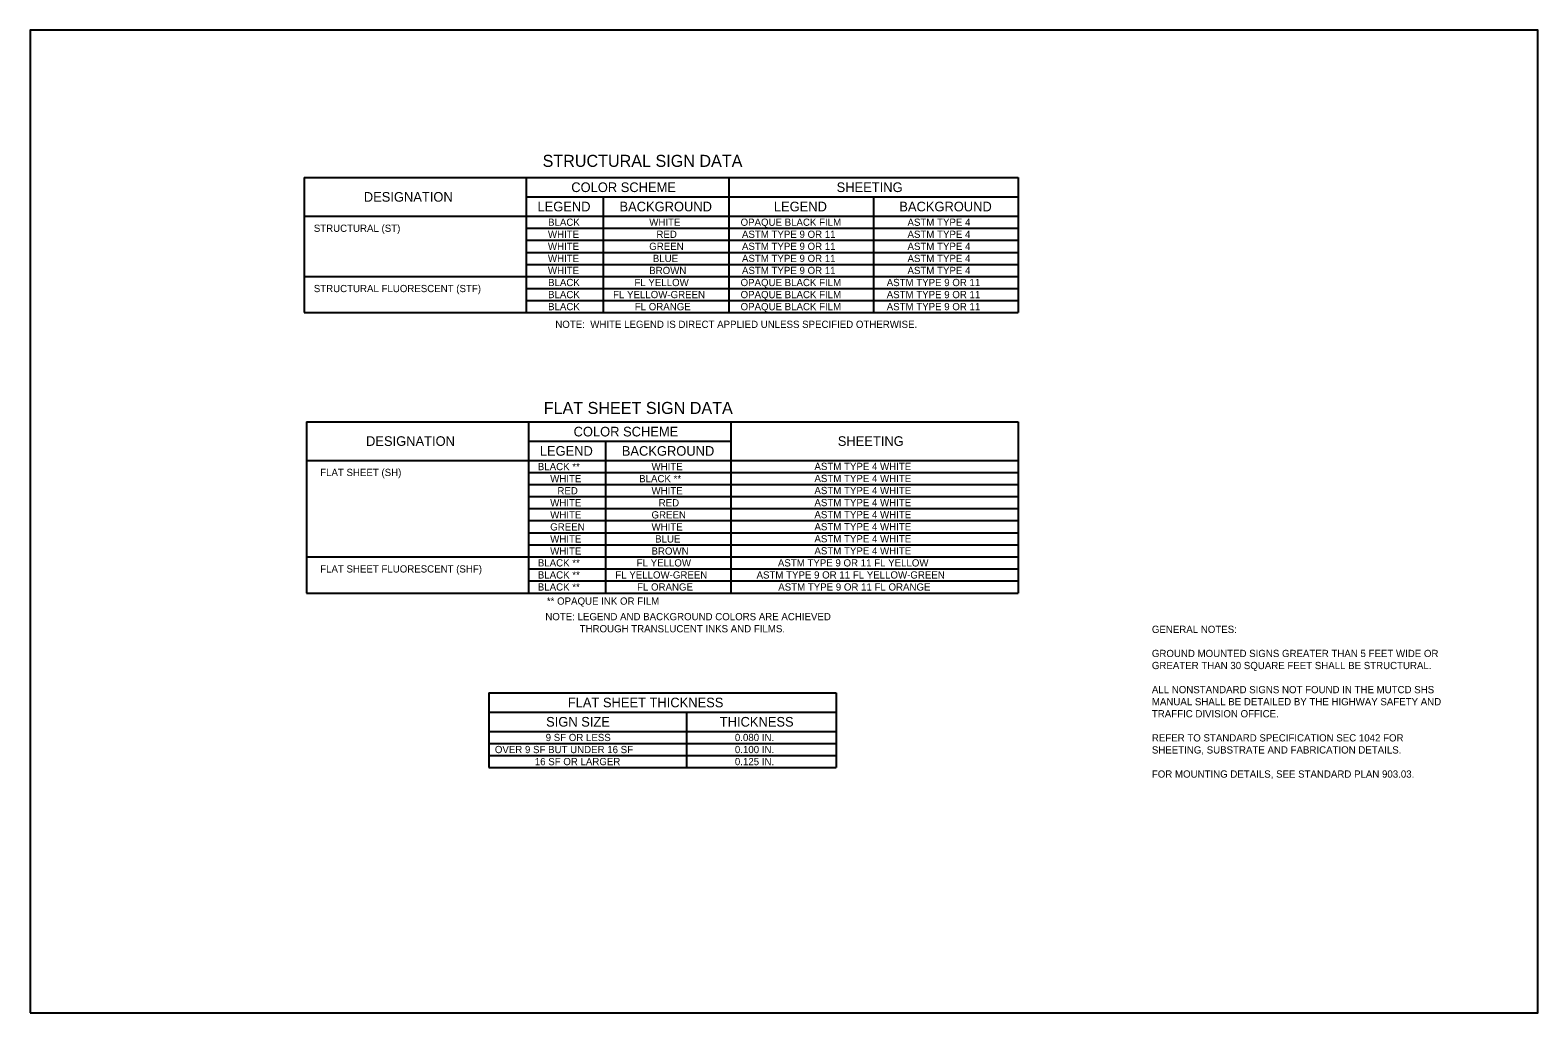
# Model space of a CAD drawing. Extents: x -439.1 to -407.9, y -458.1 to -437.7.
import ezdxf

# ---------------------------------------------------------------- set-up
doc = ezdxf.new("R2010")
doc.units = 0
for name, color, linetype in [('Draft_Named_Boundary', 7, 'Continuous'), ('Level 4', 7, 'Continuous'), ('Level 45', 7, 'Continuous')]:
    doc.layers.add(name, color=color, linetype=linetype)

msp = doc.modelspace()

# ---------------------------------------------------------------- linework, layer by layer
at = {"layer": 'Draft_Named_Boundary'}
msp.add_lwpolyline([(-439.109, -458.051), (-407.859, -458.051), (-407.859, -437.676), (-439.109, -437.676)], close=True, dxfattribs=at)
at = {"layer": 'Level 4'}
for p, q in [((-433.43, -440.733), (-433.43, -443.533)), ((-433.43, -440.733), (-418.63, -440.733)), ((-428.83, -440.733), (-428.83, -443.533)), ((-424.63, -440.733), (-424.63, -443.533)), ((-418.63, -440.733), (-418.63, -443.533)), ((-428.83, -441.133), (-418.63, -441.133)), ((-427.23, -441.133), (-427.23, -443.533)), ((-421.63, -441.133), (-421.63, -443.533)), ((-433.43, -441.533), (-418.63, -441.533)), ((-428.83, -441.783), (-418.63, -441.783)), ((-428.83, -442.033), (-418.63, -442.033)), ((-428.83, -442.283), (-418.63, -442.283)), ((-433.43, -442.783), (-418.63, -442.783)), ((-428.83, -442.533), (-418.63, -442.533)), ((-428.83, -443.033), (-418.63, -443.033)), ((-428.83, -443.283), (-418.63, -443.283)), ((-433.43, -443.533), (-418.63, -443.533)), ((-433.384, -445.796), (-433.384, -449.35)), ((-433.384, -445.796), (-418.629, -445.796)), ((-428.783, -445.8), (-428.783, -449.35)), ((-424.583, -445.8), (-424.583, -449.35)), ((-418.629, -445.796), (-418.629, -449.35)), ((-428.783, -446.196), (-424.583, -446.196)), ((-427.183, -446.2), (-427.183, -449.35)), ((-433.384, -446.596), (-418.629, -446.596)), ((-428.784, -446.846), (-418.629, -446.846)), ((-428.784, -447.096), (-418.629, -447.096)), ((-428.784, -447.346), (-418.629, -447.346)), ((-428.784, -447.596), (-418.629, -447.596)), ((-428.784, -447.846), (-418.629, -447.846)), ((-428.784, -448.096), (-418.629, -448.096)), ((-428.784, -448.346), (-418.629, -448.346)), ((-433.384, -448.596), (-418.629, -448.596)), ((-428.784, -448.846), (-418.629, -448.846)), ((-433.383, -449.35), (-418.628, -449.35)), ((-428.784, -449.096), (-418.629, -449.096)), ((-428.783, -449.096), (-418.629, -449.096)), ((-429.602, -451.416), (-429.602, -452.966)), ((-429.602, -451.416), (-422.402, -451.416)), ((-422.402, -451.416), (-422.402, -452.966)), ((-429.602, -451.816), (-422.402, -451.816)), ((-425.502, -451.816), (-425.502, -452.966)), ((-429.602, -452.216), (-422.402, -452.216)), ((-429.602, -452.466), (-422.402, -452.466)), ((-429.602, -452.716), (-422.402, -452.716)), ((-429.602, -452.966), (-422.402, -452.966))]:
    msp.add_line(p, q, dxfattribs=at)

# ---------------------------------------------------------------- texts
for s, height, p in [('STRUCTURAL SIGN DATA', 0.25, (-428.488, -440.511)), ('COLOR SCHEME', 0.2, (-427.893, -441.033)), ('SHEETING', 0.2, (-422.393, -441.033)), ('DESIGNATION', 0.2, (-432.193, -441.233)), ('LEGEND', 0.2, (-428.594, -441.433)), ('BACKGROUND', 0.2, (-426.894, -441.433)), ('LEGEND', 0.2, (-423.694, -441.433)), ('BACKGROUND', 0.2, (-421.094, -441.433)), ('STRUCTURAL (ST)', 0.15, (-433.23, -441.858)), ('WHITE', 0.15, (-428.377, -441.983)), ('BLACK', 0.15, (-428.374, -441.733)), ('WHITE', 0.15, (-426.277, -441.733)), ('RED', 0.15, (-426.128, -441.983)), ('OPAQUE BLACK FILM', 0.15, (-424.384, -441.733)), ('ASTM TYPE 9 OR 11', 0.15, (-424.355, -441.983)), ('ASTM TYPE 4', 0.15, (-420.924, -441.733)), ('ASTM TYPE 4', 0.15, (-420.924, -441.983)), ('WHITE ', 0.15, (-428.377, -442.233)), ('GREEN', 0.15, (-426.277, -442.233)), ('ASTM TYPE 9 OR 11', 0.15, (-424.355, -442.233)), ('ASTM TYPE 4', 0.15, (-420.924, -442.233)), ('WHITE', 0.15, (-428.377, -442.483)), ('BLUE', 0.15, (-426.202, -442.483)), ('ASTM TYPE 9 OR 11', 0.15, (-424.355, -442.483)), ('ASTM TYPE 4', 0.15, (-420.924, -442.483)), ('WHITE', 0.15, (-428.377, -442.733)), ('BROWN', 0.15, (-426.277, -442.733)), ('ASTM TYPE 9 OR 11', 0.15, (-424.355, -442.733)), ('ASTM TYPE 4', 0.15, (-420.924, -442.733)), ('STRUCTURAL FLUORESCENT (STF)', 0.15, (-433.23, -443.108)), ('BLACK', 0.15, (-428.374, -442.983)), ('BLACK', 0.15, (-428.374, -443.233)), ('FL YELLOW-GREEN', 0.15, (-427.027, -443.233)), ('FL YELLOW', 0.15, (-426.584, -442.983)), ('OPAQUE BLACK FILM', 0.15, (-424.384, -442.983)), ('OPAQUE BLACK FILM', 0.15, (-424.384, -443.233)), ('ASTM TYPE 9 OR 11', 0.15, (-421.355, -442.983)), ('ASTM TYPE 9 OR 11', 0.15, (-421.355, -443.233)), ('BLACK', 0.15, (-428.374, -443.483)), ('FL ORANGE', 0.15, (-426.577, -443.483)), ('OPAQUE BLACK FILM', 0.15, (-424.384, -443.483)), ('ASTM TYPE 9 OR 11', 0.15, (-421.355, -443.483)), ('NOTE:  WHITE LEGEND IS DIRECT APPLIED UNLESS SPECIFIED OTHERWISE.', 0.15, (-428.224, -443.85)), ('FLAT SHEET SIGN DATA', 0.25, (-428.465, -445.634)), ('COLOR SCHEME', 0.2, (-427.845, -446.1)), ('DESIGNATION', 0.2, (-432.147, -446.296)), ('SHEETING', 0.2, (-422.369, -446.296)), ('LEGEND', 0.2, (-428.546, -446.5)), ('BACKGROUND', 0.2, (-426.846, -446.5)), ('FLAT SHEET (SH)', 0.15, (-433.098, -446.921)), ('BLACK **', 0.15, (-428.586, -446.8)), ('WHITE', 0.15, (-426.23, -446.8)), ('ASTM TYPE 4 WHITE', 0.15, (-422.853, -446.796)), ('WHITE', 0.15, (-428.33, -447.05)), ('RED', 0.15, (-428.181, -447.3)), ('BLACK **', 0.15, (-426.486, -447.05)), ('WHITE', 0.15, (-426.23, -447.3)), ('ASTM TYPE 4 WHITE', 0.15, (-422.853, -447.046)), ('ASTM TYPE 4 WHITE', 0.15, (-422.853, -447.296)), ('WHITE', 0.15, (-428.33, -447.55)), ('RED', 0.15, (-426.081, -447.55)), ('ASTM TYPE 4 WHITE', 0.15, (-422.853, -447.546)), ('WHITE', 0.15, (-428.33, -447.8)), ('GREEN', 0.15, (-426.23, -447.8)), ('ASTM TYPE 4 WHITE', 0.15, (-422.853, -447.796)), ('GREEN', 0.15, (-428.33, -448.05)), ('WHITE', 0.15, (-426.23, -448.05)), ('ASTM TYPE 4 WHITE', 0.15, (-422.853, -448.046)), ('WHITE', 0.15, (-428.33, -448.3)), ('WHITE', 0.15, (-428.33, -448.55)), ('BROWN', 0.15, (-426.23, -448.55)), ('BLUE', 0.15, (-426.155, -448.3)), ('ASTM TYPE 4 WHITE', 0.15, (-422.853, -448.296)), ('ASTM TYPE 4 WHITE', 0.15, (-422.853, -448.546)), ('BLACK **', 0.15, (-428.586, -448.796)), ('FL YELLOW', 0.15, (-426.537, -448.796)), ('ASTM TYPE 9 OR 11 FL YELLOW', 0.15, (-423.61, -448.796)), ('FLAT SHEET FLUORESCENT (SHF)', 0.15, (-433.098, -448.921)), ('BLACK **', 0.15, (-428.586, -449.046)), ('FL YELLOW-GREEN', 0.15, (-426.98, -449.046)), ('ASTM TYPE 9 OR 11 FL YELLOW-GREEN', 0.15, (-424.053, -449.046)), ('BLACK **', 0.15, (-428.586, -449.296)), ('FL ORANGE', 0.15, (-426.53, -449.296)), ('ASTM TYPE 9 OR 11 FL ORANGE', 0.15, (-423.603, -449.296)), ('** OPAQUE INK OR FILM', 0.15, (-428.399, -449.588)), ('NOTE: LEGEND AND BACKGROUND COLORS ARE ACHIEVED ', 0.15, (-428.431, -449.911)), ('  THROUGH TRANSLUCENT INKS AND FILMS.', 0.15, (-427.831, -450.161)), ('FLAT SHEET THICKNESS', 0.2, (-427.965, -451.716)), ('SIGN SIZE', 0.2, (-428.415, -452.116)), ('THICKNESS', 0.2, (-424.815, -452.116)), ('9 SF OR LESS', 0.15, (-428.424, -452.416)), ('0.080 IN.', 0.15, (-424.502, -452.416)), ('OVER 9 SF BUT UNDER 16 SF ', 0.15, (-429.477, -452.666)), ('16 SF OR LARGER', 0.15, (-428.649, -452.916)), ('0.100 IN.', 0.15, (-424.502, -452.666)), ('0.125 IN.', 0.15, (-424.502, -452.916))]:
    msp.add_text(s, height=height, dxfattribs=at).set_placement(p)
at = {"layer": 'Level 45'}
for s, p in [('GENERAL NOTES:', (-415.859, -450.174)), ('GROUND MOUNTED SIGNS GREATER THAN 5 FEET WIDE OR ', (-415.859, -450.674)), ('GREATER THAN 30 SQUARE FEET SHALL BE STRUCTURAL.', (-415.859, -450.924)), ('ALL NONSTANDARD SIGNS NOT FOUND IN THE MUTCD SHS', (-415.859, -451.424)), ('MANUAL SHALL BE DETAILED BY THE HIGHWAY SAFETY AND', (-415.859, -451.674)), ('TRAFFIC DIVISION OFFICE.', (-415.859, -451.924)), ('REFER TO STANDARD SPECIFICATION SEC 1042 FOR', (-415.859, -452.424)), ('SHEETING, SUBSTRATE AND FABRICATION DETAILS.', (-415.859, -452.674)), ('FOR MOUNTING DETAILS, SEE STANDARD PLAN 903.03.', (-415.859, -453.174))]:
    msp.add_text(s, height=0.15, dxfattribs=at).set_placement(p)

doc.saveas('drawing.dxf')
